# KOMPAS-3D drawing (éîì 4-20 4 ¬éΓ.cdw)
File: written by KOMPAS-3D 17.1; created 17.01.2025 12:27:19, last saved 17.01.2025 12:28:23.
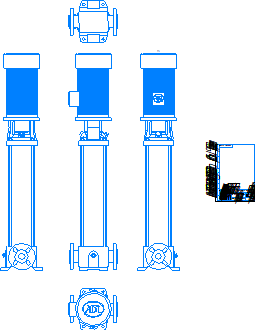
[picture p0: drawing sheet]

Sheet 1: A4, portrait

Title block, sheet 1: name: ВМН 4-20 4 кВт; designation: ВМН 4-20 4 кВт; material: Сталь 10  ГОСТ 1050-2013; mass: 53,6; sheets: 1; sheet format: A4; stored path: \\adlc.lan\data\АДЛ_ПКД\3D-модели\ADL production\Насосы ГРАНПАМП\Насосы ВМН\ВМН4\KOMPAS 3D\ВМН 4-20 4 кВт.cdw

Views: Вид 1, Спереди, Проекционный вид 2, Проекционный вид 3, Проекционный вид 4, Проекционный вид 5
Referenced files in \\adlc.lan\data\АДЛ_ПКД\3D-модели\ADL production\Насосы ГРАНПАМП\Насосы ВМН\ВМН4\KOMPAS 3D\: ВМН 4-20 4 кВт.m3d
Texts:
  Andrey
  АДЛ
Dimensions and other numbers on the sheet: 1:1; 1; 53,6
